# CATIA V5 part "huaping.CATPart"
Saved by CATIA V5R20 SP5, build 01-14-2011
Part number: 花瓶
Material "DS star": density 1000 kg/m3
Bounding box of the stored display mesh (mm): x -17.468 to 17.468, y -17.468 to 24.692, z -0.18 to 114.142
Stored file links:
  E:\180522127 徐丽维\huaping.CATPart
  C:\Program Files\Dassault Systemes\B20\intel_a\startup\materials\Catalog.CATMaterial
  C:\Program Files\Dassault Systemes\B20\intel_a\startup\materials\canvas.png
  C:\Program Files\Dassault Systemes\B20\intel_a\startup\materials\rainy_sky.jpg
  C:\Program Files\Dassault Systemes\B20\intel_a\startup\materials\strip_wall.jpg
  C:\Program Files\Dassault Systemes\B20\intel_a\startup\materials\sunset.jpg
  C:\Program Files\Dassault Systemes\B20\intel_a\startup\materials\DS_star.jpg
  C:\Program Files\Dassault Systemes\B20\intel_a\startup\materials\raw_polystyren.jpg
  C:\Program Files\Dassault Systemes\B20\intel_a\startup\materials\marble_3.jpg
  C:\Program Files\Dassault Systemes\B20\intel_a\startup\materials\alabaster.jpg
  C:\Program Files\Dassault Systemes\B20\intel_a\startup\materials\granite.jpg
  C:\Program Files\Dassault Systemes\B20\intel_a\startup\materials\flint.jpg
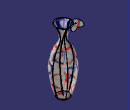
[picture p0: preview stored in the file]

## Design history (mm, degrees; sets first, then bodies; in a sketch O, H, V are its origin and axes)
Body1 (main body), material "DS star"
  Plane1: type Offset, RefPlane xy-plane, Offset 20
  Plane2: type Offset, RefPlane Plane1, Offset 20
  Plane3: type Offset, RefPlane Plane2, Offset 20
  Plane4: type Offset, RefPlane Plane3, Offset 20
  Plane5: type Offset, RefPlane Plane4, Offset 20
  Sketch1 on Plane5, origin (0, 0, 100), H (1, 0, 0), V (0, 1, 0)
    circle A1 centre (0, 0) radius 12
    point P1 (12, 0)
    radius A1 = 12
    coincidence: A1 P1, P1 H
  Sketch2 on Plane4, origin (0, 0, 80), H (1, 0, 0), V (0, 1, 0)
    circle A1 centre (0, 0) radius 5
    radius A1 = 5
  Sketch3 on Plane3, origin (0, 0, 60), H (1, 0, 0), V (0, 1, 0)
    circle A1 centre (0, 0) radius 14
    radius A1 = 14
  Sketch4 on Plane2, origin (0, 0, 40), H (1, 0, 0), V (0, 1, 0)
    circle A1 centre (0, 0) radius 17.5
    radius A1 = 17.5
  Sketch5 on Plane1, origin (0, 0, 20), H (1, 0, 0), V (0, 1, 0)
    circle A1 centre (0, 0) radius 15
    radius A1 = 15
  Sketch6 on xy-plane, origin (0, 0, 0), H (1, 0, 0), V (0, 1, 0)
    circle A1 centre (0, 0) radius 9
    radius A1 = 9
  Loft1: solid, Sections (Sketch1; Sketch2; Sketch3; Sketch4; Sketch5; Sketch6)
  Shell1: ExtOffset 0, Face face of Loft1, IntOffset 1
  Sketch7 on yz-plane, origin (0, 0, 0), H (0, 1, 0), V (0, 0, 1)
    spline S1 through (0, 0) (0, 80) (10, 100) (20, 110)
    point P1 (0, 0)
    point P2 (0, 80)
    coincidence: P1 O, P2 V
  Point1: type OnCurve, Support Sketch7, Length 117.6292
  Plane6: type Normal, Curve Sketch7, RefPoint Point1
  Circle1: type CtrRad, Start 0, End 180, Radius 0.7, Center Point1, Support Plane6, FirstDirection (1, 0, 0)
  Rib1: profile Circle1, centre curve Sketch7
  Sketch8 on Plane6, origin (0, 65.7061, 50.3277), H (1, 0, 0), V (0, -0.6081, 0.7939)
    spline S1 through (0, 70) (10, 70) (0, 80) (-10, 70) (0, 70)
    point P1 (0, 70)
    point P2 (0, 70)
    coincidence: P1 V, P2 P1
  Pad1: profile Sketch8, direction (0, 0.7939, 0.6081), length 0.5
